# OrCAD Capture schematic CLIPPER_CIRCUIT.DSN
size A
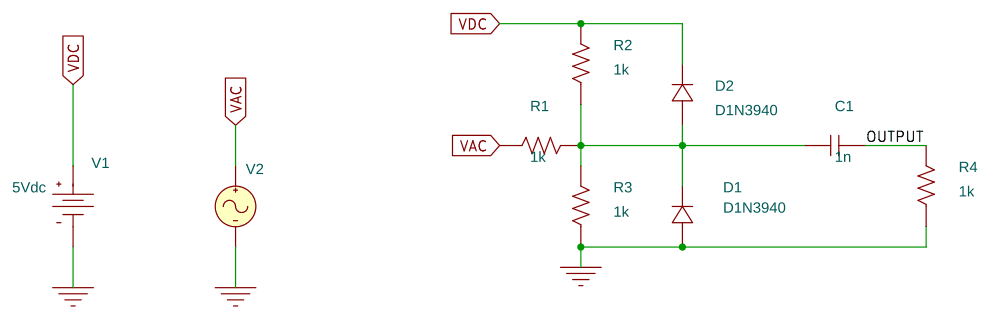
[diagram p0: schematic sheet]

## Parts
C1  1n  [CK05]
D1  D1N3940  [dax1375x070034]
D2  D1N3940  [dax1375x070034]
R1  1k  [RC05]
R2  1k  [RC05]
R3  1k  [RC05]
R4  1k  [RC05]
V1  VDC
V2  VAC

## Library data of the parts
C1 = C
D1 D2 = D1N3940
R1-R4 = R
V1 = VDC: DC: 5Vdc
V2 = VAC

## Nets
0: D1.1 R3.1 R4.1 V1.1(-) V2.2(-)
OUTPUT: C1.2 R4.2
VAC: R1.1 V2.1(+)
VDC: D2.2 R2.2 V1.0(+)
N00221: C1.1 D1.2 D2.1 R1.2 R2.1 R3.2
